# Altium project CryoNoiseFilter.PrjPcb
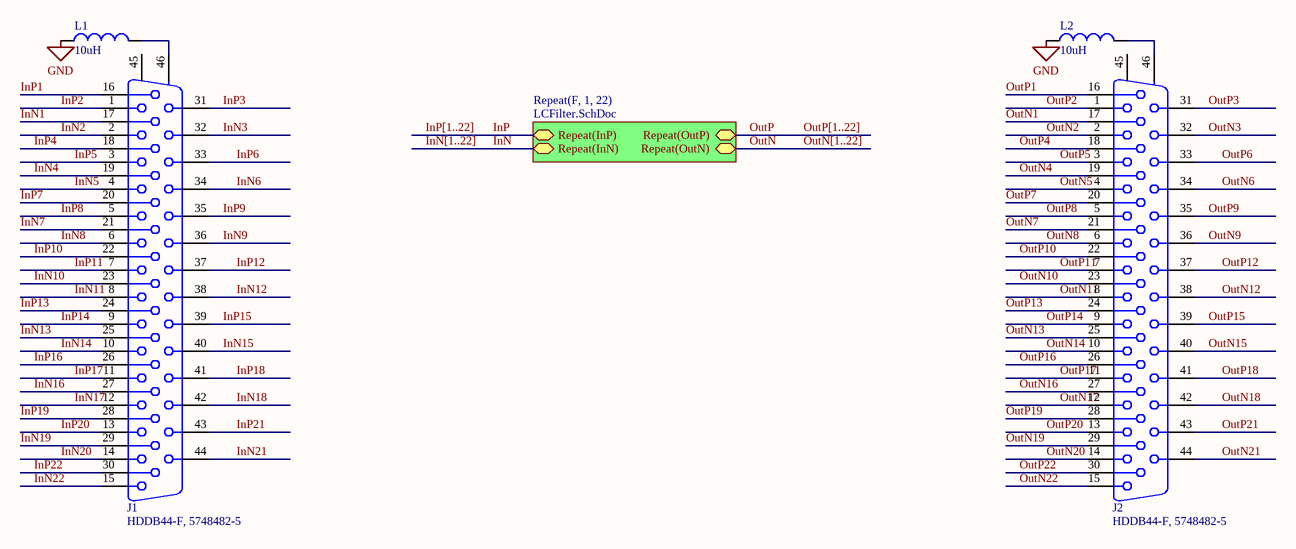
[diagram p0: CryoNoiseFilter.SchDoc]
2 sheets, 246 parts. Net scope: hierarchical (ports join the sheet entries above them; power ports are global).
Board files: CryoNoiseFilter.PcbDoc, CryoNoiseFilterArray.PcbDoc
Sheets:
  CryoNoiseFilter.SchDoc
    F1 = LCFilter.SchDoc
    F2 = LCFilter.SchDoc
    F3 = LCFilter.SchDoc
    F4 = LCFilter.SchDoc
    F5 = LCFilter.SchDoc
    F6 = LCFilter.SchDoc
    F7 = LCFilter.SchDoc
    F8 = LCFilter.SchDoc
    F9 = LCFilter.SchDoc
    F10 = LCFilter.SchDoc
    F11 = LCFilter.SchDoc
    F12 = LCFilter.SchDoc
    F13 = LCFilter.SchDoc
    F14 = LCFilter.SchDoc
    F15 = LCFilter.SchDoc
    F16 = LCFilter.SchDoc
    F17 = LCFilter.SchDoc
    F18 = LCFilter.SchDoc
    F19 = LCFilter.SchDoc
    F20 = LCFilter.SchDoc
    F21 = LCFilter.SchDoc
    F22 = LCFilter.SchDoc

## Sheet CryoNoiseFilter.SchDoc
size A4

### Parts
J1  HDDB44-F, 5748482-5  [DSUBHD44]
J2  HDDB44-F, 5748482-5  [DSUBHD44]
L1  10uH  [0805]
L2  10uH  [0805]

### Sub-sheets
Repeat(F, 1, 22) = LCFilter.SchDoc: Repeat(InP), Repeat(InN), Repeat(OutP), Repeat(OutN)

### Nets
GND: L1.1 L2.1
InN1: J1.17
InN2: J1.2
InN3: J1.32
InN4: J1.19
InN5: J1.4
InN6: J1.34
InN7: J1.21
InN8: J1.6
InN9: J1.36
InN10: J1.23
InN11: J1.8
InN12: J1.38
InN13: J1.25
InN14: J1.10
InN15: J1.40
InN16: J1.27
InN17: J1.12
InN18: J1.42
InN19: J1.29
InN20: J1.14
InN21: J1.44
InN22: J1.15
InP1: J1.16
InP2: J1.1
InP3: J1.31
InP4: J1.18
InP5: J1.3
InP6: J1.33
InP7: J1.20
InP8: J1.5
InP9: J1.35
InP10: J1.22
InP11: J1.7
InP12: J1.37
InP13: J1.24
InP14: J1.9
InP15: J1.39
InP16: J1.26
InP17: J1.11
InP18: J1.41
InP19: J1.28
InP20: J1.13
InP21: J1.43
InP22: J1.30
OutN1: J2.17
OutN2: J2.2
OutN3: J2.32
OutN4: J2.19
OutN5: J2.4
OutN6: J2.34
OutN7: J2.21
OutN8: J2.6
OutN9: J2.36
OutN10: J2.23
OutN11: J2.8
OutN12: J2.38
OutN13: J2.25
OutN14: J2.10
OutN15: J2.40
OutN16: J2.27
OutN17: J2.12
OutN18: J2.42
OutN19: J2.29
OutN20: J2.14
OutN21: J2.44
OutN22: J2.15
OutP1: J2.16
OutP2: J2.1
OutP3: J2.31
OutP4: J2.18
OutP5: J2.3
OutP6: J2.33
OutP7: J2.20
OutP8: J2.5
OutP9: J2.35
OutP10: J2.22
OutP11: J2.7
OutP12: J2.37
OutP13: J2.24
OutP14: J2.9
OutP15: J2.39
OutP16: J2.26
OutP17: J2.11
OutP18: J2.41
OutP19: J2.28
OutP20: J2.13
OutP21: J2.43
OutP22: J2.30
NetJ1_46: J1.46 L1.2
NetJ2_46: J2.46 L2.2

Not connected (* = marked no-connect by the designer): J1 45; J2 45

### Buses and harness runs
bus InN[1..22]
bus InP[1..22]
bus OutN[1..22]
bus OutP[1..22]

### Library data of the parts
J1 J2 = DB44HD-F: CONN, High Density DB44 Female; Manufacturer: Tyco Electronics
L1 L2 = Inductor0: Inductor 47uH, 5.46 Ohm, 0.1A, 0805; Manufacturer: Taiyo Yuden; Manufacturers P/N: CBL2012T470M

## Sheet LCFilter.SchDoc
size A4
Used 22 times, as channels F1, F2, F3, F4, F5, F6, F7, F8, F9, F10, F11, F12, F13, F14, F15, F16, F17, F18, F19, F20, F21, F22. Parts and nets are listed once, with the designators drawn on the sheet.
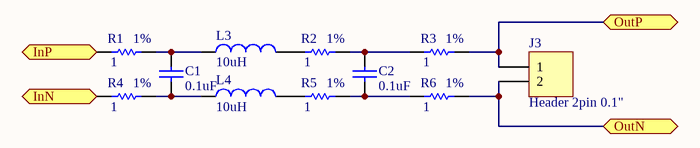
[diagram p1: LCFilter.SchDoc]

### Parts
C1  0.1uF  [0805]
C2  0.1uF  [0805]
J3  Header 2pin 0.1"  [HDR1X2]
L3  10uH  [0805]
L4  10uH  [0805]
R1  value 1  Param: 1%  [0805]  (hidden comment: 0805)
R2  value 1  Param: 1%  [0805]  (hidden comment: 0805)
R3  value 1  Param: 1%  [0805]  (hidden comment: 0805)
R4  value 1  Param: 1%  [0805]  (hidden comment: 0805)
R5  value 1  Param: 1%  [0805]  (hidden comment: 0805)
R6  value 1  Param: 1%  [0805]  (hidden comment: 0805)

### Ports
InN, InP, OutN, OutP

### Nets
InN: R4.1 ; port InN
InP: R1.1 ; port InP
OutN: J3.2 R6.2 ; port OutN
OutP: J3.1 R3.2 ; port OutP
NetC1_1: C1.1 L4.1 R4.2
NetC1_2: C1.2 L3.1 R1.2
NetC2_1: C2.1 R5.2 R6.1
NetC2_2: C2.2 R2.2 R3.1
NetL3_2: L3.2 R2.1
NetL4_2: L4.2 R5.1

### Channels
F1: designators end in _F1; ports InN=InN1 InP=InP1 OutN=OutN1 OutP=OutP1
F2: designators end in _F2; ports InN=InN2 InP=InP2 OutN=OutN2 OutP=OutP2
F3: designators end in _F3; ports InN=InN3 InP=InP3 OutN=OutN3 OutP=OutP3
F4: designators end in _F4; ports InN=InN4 InP=InP4 OutN=OutN4 OutP=OutP4
F5: designators end in _F5; ports InN=InN5 InP=InP5 OutN=OutN5 OutP=OutP5
F6: designators end in _F6; ports InN=InN6 InP=InP6 OutN=OutN6 OutP=OutP6
F7: designators end in _F7; ports InN=InN7 InP=InP7 OutN=OutN7 OutP=OutP7
F8: designators end in _F8; ports InN=InN8 InP=InP8 OutN=OutN8 OutP=OutP8
F9: designators end in _F9; ports InN=InN9 InP=InP9 OutN=OutN9 OutP=OutP9
F10: designators end in _F10; ports InN=InN10 InP=InP10 OutN=OutN10 OutP=OutP10
F11: designators end in _F11; ports InN=InN11 InP=InP11 OutN=OutN11 OutP=OutP11
F12: designators end in _F12; ports InN=InN12 InP=InP12 OutN=OutN12 OutP=OutP12
F13: designators end in _F13; ports InN=InN13 InP=InP13 OutN=OutN13 OutP=OutP13
F14: designators end in _F14; ports InN=InN14 InP=InP14 OutN=OutN14 OutP=OutP14
F15: designators end in _F15; ports InN=InN15 InP=InP15 OutN=OutN15 OutP=OutP15
F16: designators end in _F16; ports InN=InN16 InP=InP16 OutN=OutN16 OutP=OutP16
F17: designators end in _F17; ports InN=InN17 InP=InP17 OutN=OutN17 OutP=OutP17
F18: designators end in _F18; ports InN=InN18 InP=InP18 OutN=OutN18 OutP=OutP18
F19: designators end in _F19; ports InN=InN19 InP=InP19 OutN=OutN19 OutP=OutP19
F20: designators end in _F20; ports InN=InN20 InP=InP20 OutN=OutN20 OutP=OutP20
F21: designators end in _F21; ports InN=InN21 InP=InP21 OutN=OutN21 OutP=OutP21
F22: designators end in _F22; ports InN=InN22 InP=InP22 OutN=OutN22 OutP=OutP22

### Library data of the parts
C1 C2 = Cap0603: Capacitor, Ceramic, 0803
J3 = Header2: Header, 0.1", 2-Pin straight (Any equivalent - may need to be value added); Manufacturer: Digikey; Manufacturers P/N: A26508-02-ND
L3 L4 = Inductor0: as L1 on sheet CryoNoiseFilter
R1-R6 = Res0603: Resistor; Param1: 100ppm/C

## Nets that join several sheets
InN1: CryoNoiseFilter (J1.17), F1 (R4_F1.1)
InN2: CryoNoiseFilter (J1.2), F2 (R4_F2.1)
InN3: CryoNoiseFilter (J1.32), F3 (R4_F3.1)
InN4: CryoNoiseFilter (J1.19), F4 (R4_F4.1)
InN5: CryoNoiseFilter (J1.4), F5 (R4_F5.1)
InN6: CryoNoiseFilter (J1.34), F6 (R4_F6.1)
InN7: CryoNoiseFilter (J1.21), F7 (R4_F7.1)
InN8: CryoNoiseFilter (J1.6), F8 (R4_F8.1)
InN9: CryoNoiseFilter (J1.36), F9 (R4_F9.1)
InN10: CryoNoiseFilter (J1.23), F10 (R4_F10.1)
InN11: CryoNoiseFilter (J1.8), F11 (R4_F11.1)
InN12: CryoNoiseFilter (J1.38), F12 (R4_F12.1)
InN13: CryoNoiseFilter (J1.25), F13 (R4_F13.1)
InN14: CryoNoiseFilter (J1.10), F14 (R4_F14.1)
InN15: CryoNoiseFilter (J1.40), F15 (R4_F15.1)
InN16: CryoNoiseFilter (J1.27), F16 (R4_F16.1)
InN17: CryoNoiseFilter (J1.12), F17 (R4_F17.1)
InN18: CryoNoiseFilter (J1.42), F18 (R4_F18.1)
InN19: CryoNoiseFilter (J1.29), F19 (R4_F19.1)
InN20: CryoNoiseFilter (J1.14), F20 (R4_F20.1)
InN21: CryoNoiseFilter (J1.44), F21 (R4_F21.1)
InN22: CryoNoiseFilter (J1.15), F22 (R4_F22.1)
InP1: CryoNoiseFilter (J1.16), F1 (R1_F1.1)
InP2: CryoNoiseFilter (J1.1), F2 (R1_F2.1)
InP3: CryoNoiseFilter (J1.31), F3 (R1_F3.1)
InP4: CryoNoiseFilter (J1.18), F4 (R1_F4.1)
InP5: CryoNoiseFilter (J1.3), F5 (R1_F5.1)
InP6: CryoNoiseFilter (J1.33), F6 (R1_F6.1)
InP7: CryoNoiseFilter (J1.20), F7 (R1_F7.1)
InP8: CryoNoiseFilter (J1.5), F8 (R1_F8.1)
InP9: CryoNoiseFilter (J1.35), F9 (R1_F9.1)
InP10: CryoNoiseFilter (J1.22), F10 (R1_F10.1)
InP11: CryoNoiseFilter (J1.7), F11 (R1_F11.1)
InP12: CryoNoiseFilter (J1.37), F12 (R1_F12.1)
InP13: CryoNoiseFilter (J1.24), F13 (R1_F13.1)
InP14: CryoNoiseFilter (J1.9), F14 (R1_F14.1)
InP15: CryoNoiseFilter (J1.39), F15 (R1_F15.1)
InP16: CryoNoiseFilter (J1.26), F16 (R1_F16.1)
InP17: CryoNoiseFilter (J1.11), F17 (R1_F17.1)
InP18: CryoNoiseFilter (J1.41), F18 (R1_F18.1)
InP19: CryoNoiseFilter (J1.28), F19 (R1_F19.1)
InP20: CryoNoiseFilter (J1.13), F20 (R1_F20.1)
InP21: CryoNoiseFilter (J1.43), F21 (R1_F21.1)
InP22: CryoNoiseFilter (J1.30), F22 (R1_F22.1)
OutN1: CryoNoiseFilter (J2.17), F1 (J3_F1.2 R6_F1.2)
OutN2: CryoNoiseFilter (J2.2), F2 (J3_F2.2 R6_F2.2)
OutN3: CryoNoiseFilter (J2.32), F3 (J3_F3.2 R6_F3.2)
OutN4: CryoNoiseFilter (J2.19), F4 (J3_F4.2 R6_F4.2)
OutN5: CryoNoiseFilter (J2.4), F5 (J3_F5.2 R6_F5.2)
OutN6: CryoNoiseFilter (J2.34), F6 (J3_F6.2 R6_F6.2)
OutN7: CryoNoiseFilter (J2.21), F7 (J3_F7.2 R6_F7.2)
OutN8: CryoNoiseFilter (J2.6), F8 (J3_F8.2 R6_F8.2)
OutN9: CryoNoiseFilter (J2.36), F9 (J3_F9.2 R6_F9.2)
OutN10: CryoNoiseFilter (J2.23), F10 (J3_F10.2 R6_F10.2)
OutN11: CryoNoiseFilter (J2.8), F11 (J3_F11.2 R6_F11.2)
OutN12: CryoNoiseFilter (J2.38), F12 (J3_F12.2 R6_F12.2)
OutN13: CryoNoiseFilter (J2.25), F13 (J3_F13.2 R6_F13.2)
OutN14: CryoNoiseFilter (J2.10), F14 (J3_F14.2 R6_F14.2)
OutN15: CryoNoiseFilter (J2.40), F15 (J3_F15.2 R6_F15.2)
OutN16: CryoNoiseFilter (J2.27), F16 (J3_F16.2 R6_F16.2)
OutN17: CryoNoiseFilter (J2.12), F17 (J3_F17.2 R6_F17.2)
OutN18: CryoNoiseFilter (J2.42), F18 (J3_F18.2 R6_F18.2)
OutN19: CryoNoiseFilter (J2.29), F19 (J3_F19.2 R6_F19.2)
OutN20: CryoNoiseFilter (J2.14), F20 (J3_F20.2 R6_F20.2)
OutN21: CryoNoiseFilter (J2.44), F21 (J3_F21.2 R6_F21.2)
OutN22: CryoNoiseFilter (J2.15), F22 (J3_F22.2 R6_F22.2)
OutP1: CryoNoiseFilter (J2.16), F1 (J3_F1.1 R3_F1.2)
OutP2: CryoNoiseFilter (J2.1), F2 (J3_F2.1 R3_F2.2)
OutP3: CryoNoiseFilter (J2.31), F3 (J3_F3.1 R3_F3.2)
OutP4: CryoNoiseFilter (J2.18), F4 (J3_F4.1 R3_F4.2)
OutP5: CryoNoiseFilter (J2.3), F5 (J3_F5.1 R3_F5.2)
OutP6: CryoNoiseFilter (J2.33), F6 (J3_F6.1 R3_F6.2)
OutP7: CryoNoiseFilter (J2.20), F7 (J3_F7.1 R3_F7.2)
OutP8: CryoNoiseFilter (J2.5), F8 (J3_F8.1 R3_F8.2)
OutP9: CryoNoiseFilter (J2.35), F9 (J3_F9.1 R3_F9.2)
OutP10: CryoNoiseFilter (J2.22), F10 (J3_F10.1 R3_F10.2)
OutP11: CryoNoiseFilter (J2.7), F11 (J3_F11.1 R3_F11.2)
OutP12: CryoNoiseFilter (J2.37), F12 (J3_F12.1 R3_F12.2)
OutP13: CryoNoiseFilter (J2.24), F13 (J3_F13.1 R3_F13.2)
OutP14: CryoNoiseFilter (J2.9), F14 (J3_F14.1 R3_F14.2)
OutP15: CryoNoiseFilter (J2.39), F15 (J3_F15.1 R3_F15.2)
OutP16: CryoNoiseFilter (J2.26), F16 (J3_F16.1 R3_F16.2)
OutP17: CryoNoiseFilter (J2.11), F17 (J3_F17.1 R3_F17.2)
OutP18: CryoNoiseFilter (J2.41), F18 (J3_F18.1 R3_F18.2)
OutP19: CryoNoiseFilter (J2.28), F19 (J3_F19.1 R3_F19.2)
OutP20: CryoNoiseFilter (J2.13), F20 (J3_F20.1 R3_F20.2)
OutP21: CryoNoiseFilter (J2.43), F21 (J3_F21.1 R3_F21.2)
OutP22: CryoNoiseFilter (J2.30), F22 (J3_F22.1 R3_F22.2)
